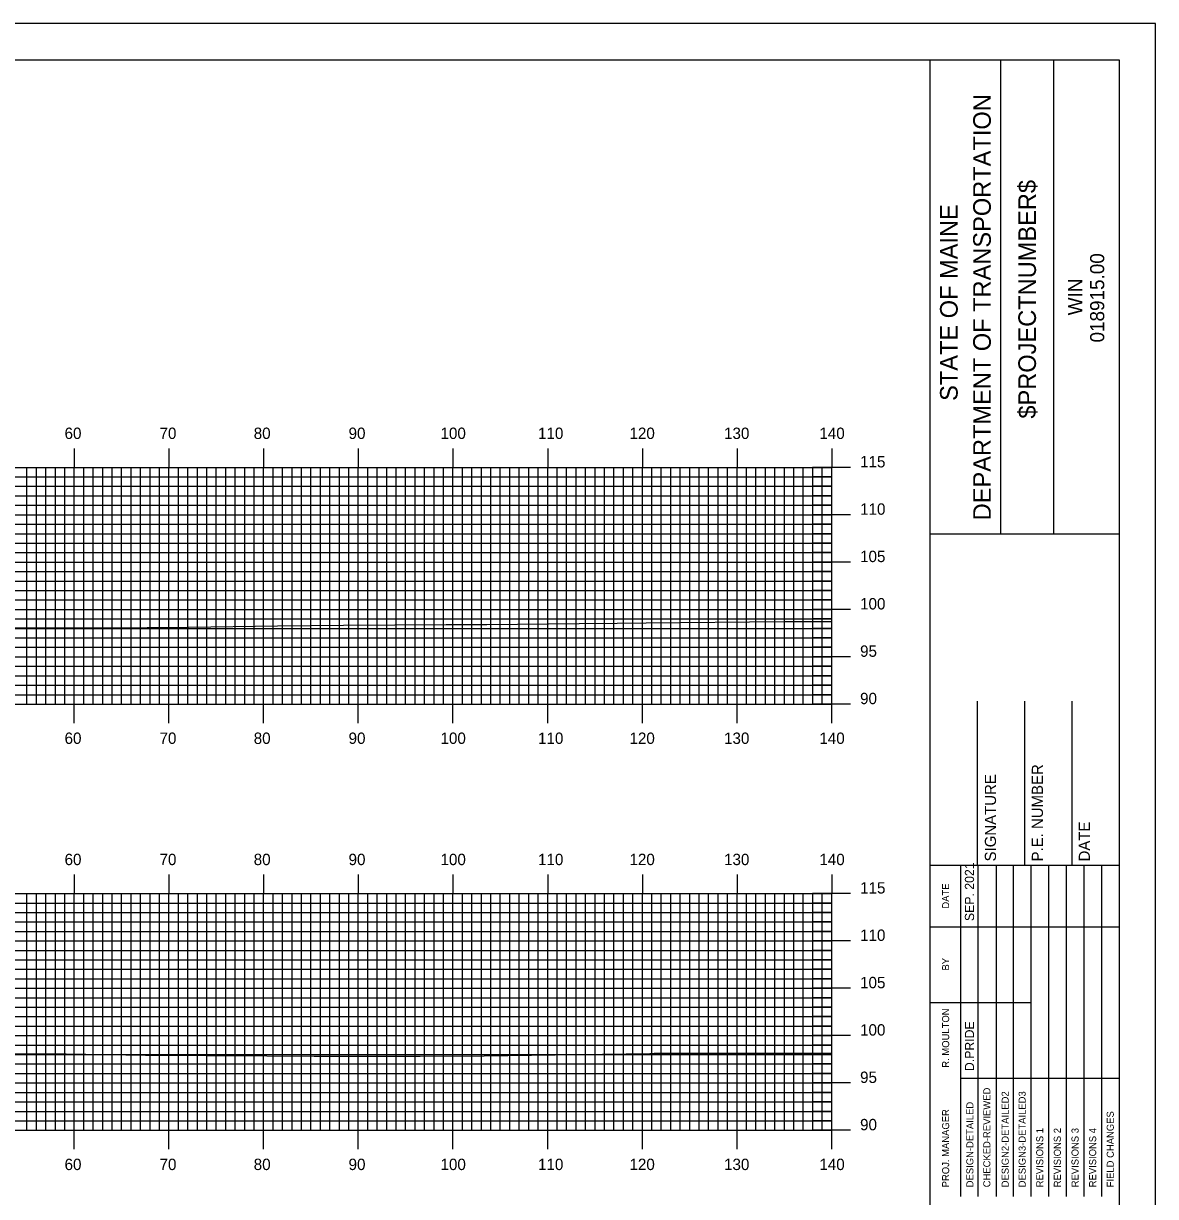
# Model space of a CAD drawing. Extents: x 1764939 to 1765282, y 442591 to 442811.
# Drawn here: x 1765159.5 to 1765279.1, y 442686.7 to 442810.5 of the extents above; entities that cross this region are included whole.
import ezdxf

# ---------------------------------------------------------------- set-up
doc = ezdxf.new("R2010")
doc.units = 0
for name, color, linetype in [('BORDER', 7, 'Continuous'), ('H_V ANNOTATION', 7, 'Continuous'), ('MAJOR', 7, 'Continuous'), ('MINOR', 7, 'Continuous'), ('PLOT BOUNDARY', 7, 'Continuous'), ('S_Roadway_Centerline', 7, 'Continuous')]:
    doc.layers.add(name, color=color, linetype=linetype)

msp = doc.modelspace()

# ---------------------------------------------------------------- linework, layer by layer
at = {"layer": 'BORDER'}
for p, q in [((1765255.26, 442596.67), (1765255.26, 442806.67)), ((1765262.72, 442756.66), (1765262.72, 442806.66)), ((1765268.31, 442756.66), (1765268.31, 442806.66)), ((1765255.26, 442756.65), (1765275.26, 442756.65)), ((1765260.26, 442721.67), (1765260.26, 442738.97)), ((1765265.26, 442721.67), (1765265.26, 442738.97)), ((1765270.26, 442721.67), (1765270.26, 442738.97)), ((1765255.26, 442721.67), (1765275.26, 442721.67))]:
    msp.add_line(p, q, dxfattribs=at)
msp.add_lwpolyline([(1764955.26, 442596.67), (1765275.26, 442596.67), (1765275.26, 442806.67), (1764955.26, 442806.67)], close=True, dxfattribs=at)
for points in [[(1765258.49, 442715.17), (1765258.49, 442721.67)], [(1765260.35, 442686.68), (1765260.35, 442721.67)], [(1765262.22, 442721.67), (1765262.22, 442686.68)], [(1765264.08, 442686.68), (1765264.08, 442721.67)], [(1765265.94, 442686.68), (1765265.94, 442721.67)], [(1765267.81, 442686.68), (1765267.81, 442721.67)], [(1765269.67, 442686.68), (1765269.67, 442721.67)], [(1765271.53, 442686.68), (1765271.53, 442721.67)], [(1765273.4, 442686.68), (1765273.4, 442721.67)], [(1765258.49, 442686.68), (1765258.49, 442720.26)], [(1765255.26, 442715.17), (1765275.26, 442715.17)], [(1765255.26, 442707.17), (1765258.49, 442707.17)], [(1765258.49, 442707.17), (1765265.94, 442707.17)], [(1765258.49, 442699.17), (1765275.26, 442699.17)]]:
    msp.add_lwpolyline(points, dxfattribs=at)
at = {"layer": 'MAJOR'}
for p, q in [((1765164.86, 442765.67), (1765164.86, 442763.67)), ((1765174.86, 442765.67), (1765174.86, 442763.67)), ((1765184.86, 442765.67), (1765184.86, 442763.67)), ((1765194.86, 442765.67), (1765194.86, 442763.67)), ((1765204.86, 442765.67), (1765204.86, 442763.67)), ((1765214.86, 442765.67), (1765214.86, 442763.67)), ((1765224.86, 442765.67), (1765224.86, 442763.67)), ((1765234.86, 442765.67), (1765234.86, 442763.67)), ((1765244.86, 442765.67), (1765244.86, 442763.67)), ((1764964.86, 442763.67), (1765244.86, 442763.67)), ((1764964.86, 442763.67), (1765244.86, 442763.67)), ((1765164.86, 442738.67), (1765164.86, 442763.67)), ((1765174.86, 442738.67), (1765174.86, 442763.67)), ((1765184.86, 442738.67), (1765184.86, 442763.67)), ((1765194.86, 442738.67), (1765194.86, 442763.67)), ((1765204.86, 442738.67), (1765204.86, 442763.67)), ((1765214.86, 442738.67), (1765214.86, 442763.67)), ((1765224.86, 442738.67), (1765224.86, 442763.67)), ((1765234.86, 442738.67), (1765234.86, 442763.67)), ((1765246.86, 442763.67), (1765242.85, 442763.67)), ((1765244.86, 442738.67), (1765244.86, 442763.67)), ((1765244.86, 442738.67), (1765244.86, 442763.67)), ((1764964.86, 442758.67), (1765244.86, 442758.67)), ((1765246.86, 442758.67), (1765242.85, 442758.67)), ((1764964.86, 442753.67), (1765244.86, 442753.67)), ((1765246.86, 442753.67), (1765242.85, 442753.67)), ((1764964.86, 442748.67), (1765244.86, 442748.67)), ((1765246.86, 442748.67), (1765242.85, 442748.67)), ((1764964.86, 442743.67), (1765244.86, 442743.67)), ((1765246.86, 442743.67), (1765242.85, 442743.67)), ((1764964.86, 442738.67), (1765244.86, 442738.67)), ((1764964.86, 442738.67), (1765244.86, 442738.67)), ((1765164.86, 442736.66), (1765164.86, 442738.67)), ((1765174.86, 442736.66), (1765174.86, 442738.67)), ((1765184.86, 442736.66), (1765184.86, 442738.67)), ((1765194.86, 442736.66), (1765194.86, 442738.67)), ((1765204.86, 442736.66), (1765204.86, 442738.67)), ((1765214.86, 442736.66), (1765214.86, 442738.67)), ((1765224.86, 442736.66), (1765224.86, 442738.67)), ((1765234.86, 442736.66), (1765234.86, 442738.67)), ((1765246.86, 442738.67), (1765242.85, 442738.67)), ((1765244.86, 442736.66), (1765244.86, 442738.67)), ((1765164.86, 442720.67), (1765164.86, 442718.67)), ((1765174.86, 442720.67), (1765174.86, 442718.67)), ((1765184.86, 442720.67), (1765184.86, 442718.67)), ((1765194.86, 442720.67), (1765194.86, 442718.67)), ((1765204.86, 442720.67), (1765204.86, 442718.67)), ((1765214.86, 442720.67), (1765214.86, 442718.67)), ((1765224.86, 442720.67), (1765224.86, 442718.67)), ((1765234.86, 442720.67), (1765234.86, 442718.67)), ((1765244.86, 442720.67), (1765244.86, 442718.67)), ((1764964.86, 442718.67), (1765244.86, 442718.67)), ((1764964.86, 442718.67), (1765244.86, 442718.67)), ((1765164.86, 442693.67), (1765164.86, 442718.67)), ((1765174.86, 442693.67), (1765174.86, 442718.67)), ((1765184.86, 442693.67), (1765184.86, 442718.67)), ((1765194.86, 442693.67), (1765194.86, 442718.67)), ((1765204.86, 442693.67), (1765204.86, 442718.67)), ((1765214.86, 442693.67), (1765214.86, 442718.67)), ((1765224.86, 442693.67), (1765224.86, 442718.67)), ((1765234.86, 442693.67), (1765234.86, 442718.67)), ((1765246.86, 442718.67), (1765242.85, 442718.67)), ((1765244.86, 442693.67), (1765244.86, 442718.67)), ((1765244.86, 442693.67), (1765244.86, 442718.67)), ((1764964.86, 442713.67), (1765244.86, 442713.67)), ((1765246.86, 442713.67), (1765242.85, 442713.67)), ((1764964.86, 442708.67), (1765244.86, 442708.67)), ((1765246.86, 442708.67), (1765242.85, 442708.67)), ((1764964.86, 442703.67), (1765244.86, 442703.67)), ((1765246.86, 442703.67), (1765242.85, 442703.67)), ((1764964.86, 442698.67), (1765244.86, 442698.67)), ((1765246.86, 442698.67), (1765242.85, 442698.67)), ((1764964.86, 442693.67), (1765244.86, 442693.67)), ((1764964.86, 442693.67), (1765244.86, 442693.67)), ((1765164.86, 442691.66), (1765164.86, 442693.67)), ((1765174.86, 442691.66), (1765174.86, 442693.67)), ((1765184.86, 442691.66), (1765184.86, 442693.67)), ((1765194.86, 442691.66), (1765194.86, 442693.67)), ((1765204.86, 442691.66), (1765204.86, 442693.67)), ((1765214.86, 442691.66), (1765214.86, 442693.67)), ((1765224.86, 442691.66), (1765224.86, 442693.67)), ((1765234.86, 442691.66), (1765234.86, 442693.67)), ((1765246.86, 442693.67), (1765242.85, 442693.67)), ((1765244.86, 442691.66), (1765244.86, 442693.67))]:
    msp.add_line(p, q, dxfattribs=at)
at = {"layer": 'MINOR'}
for p, q in [((1765159.86, 442738.67), (1765159.86, 442763.67)), ((1765160.86, 442738.67), (1765160.86, 442763.67)), ((1765161.86, 442738.67), (1765161.86, 442763.67)), ((1765162.86, 442738.67), (1765162.86, 442763.67)), ((1765163.86, 442738.67), (1765163.86, 442763.67)), ((1765165.86, 442738.67), (1765165.86, 442763.67)), ((1765166.86, 442738.67), (1765166.86, 442763.67)), ((1765167.86, 442738.67), (1765167.86, 442763.67)), ((1765168.86, 442738.67), (1765168.86, 442763.67)), ((1765169.86, 442738.67), (1765169.86, 442763.67)), ((1765170.86, 442738.67), (1765170.86, 442763.67)), ((1765171.86, 442738.67), (1765171.86, 442763.67)), ((1765172.86, 442738.67), (1765172.86, 442763.67)), ((1765173.86, 442738.67), (1765173.86, 442763.67)), ((1765175.86, 442738.67), (1765175.86, 442763.67)), ((1765176.86, 442738.67), (1765176.86, 442763.67)), ((1765177.86, 442738.67), (1765177.86, 442763.67)), ((1765178.86, 442738.67), (1765178.86, 442763.67)), ((1765179.86, 442738.67), (1765179.86, 442763.67)), ((1765180.86, 442738.67), (1765180.86, 442763.67)), ((1765181.86, 442738.67), (1765181.86, 442763.67)), ((1765182.86, 442738.67), (1765182.86, 442763.67)), ((1765183.86, 442738.67), (1765183.86, 442763.67)), ((1765185.86, 442738.67), (1765185.86, 442763.67)), ((1765186.86, 442738.67), (1765186.86, 442763.67)), ((1765187.86, 442738.67), (1765187.86, 442763.67)), ((1765188.86, 442738.67), (1765188.86, 442763.67)), ((1765189.86, 442738.67), (1765189.86, 442763.67)), ((1765190.86, 442738.67), (1765190.86, 442763.67)), ((1765191.86, 442738.67), (1765191.86, 442763.67)), ((1765192.86, 442738.67), (1765192.86, 442763.67)), ((1765193.86, 442738.67), (1765193.86, 442763.67)), ((1765195.86, 442738.67), (1765195.86, 442763.67)), ((1765196.86, 442738.67), (1765196.86, 442763.67)), ((1765197.86, 442738.67), (1765197.86, 442763.67)), ((1765198.86, 442738.67), (1765198.86, 442763.67)), ((1765199.86, 442738.67), (1765199.86, 442763.67)), ((1765200.86, 442738.67), (1765200.86, 442763.67)), ((1765201.86, 442738.67), (1765201.86, 442763.67)), ((1765202.86, 442738.67), (1765202.86, 442763.67)), ((1765203.86, 442738.67), (1765203.86, 442763.67)), ((1765205.86, 442738.67), (1765205.86, 442763.67)), ((1765206.86, 442738.67), (1765206.86, 442763.67)), ((1765207.86, 442738.67), (1765207.86, 442763.67)), ((1765208.86, 442738.67), (1765208.86, 442763.67)), ((1765209.86, 442738.67), (1765209.86, 442763.67)), ((1765210.86, 442738.67), (1765210.86, 442763.67)), ((1765211.86, 442738.67), (1765211.86, 442763.67)), ((1765212.86, 442738.67), (1765212.86, 442763.67)), ((1765213.86, 442738.67), (1765213.86, 442763.67)), ((1765215.86, 442738.67), (1765215.86, 442763.67)), ((1765216.86, 442738.67), (1765216.86, 442763.67)), ((1765217.86, 442738.67), (1765217.86, 442763.67)), ((1765218.86, 442738.67), (1765218.86, 442763.67)), ((1765219.86, 442738.67), (1765219.86, 442763.67)), ((1765220.86, 442738.67), (1765220.86, 442763.67)), ((1765221.86, 442738.67), (1765221.86, 442763.67)), ((1765222.86, 442738.67), (1765222.86, 442763.67)), ((1765223.86, 442738.67), (1765223.86, 442763.67)), ((1765225.86, 442738.67), (1765225.86, 442763.67)), ((1765226.86, 442738.67), (1765226.86, 442763.67)), ((1765227.86, 442738.67), (1765227.86, 442763.67)), ((1765228.86, 442738.67), (1765228.86, 442763.67)), ((1765229.86, 442738.67), (1765229.86, 442763.67)), ((1765230.86, 442738.67), (1765230.86, 442763.67)), ((1765231.86, 442738.67), (1765231.86, 442763.67)), ((1765232.86, 442738.67), (1765232.86, 442763.67)), ((1765233.86, 442738.67), (1765233.86, 442763.67)), ((1765235.86, 442738.67), (1765235.86, 442763.67)), ((1765236.86, 442738.67), (1765236.86, 442763.67)), ((1765237.86, 442738.67), (1765237.86, 442763.67)), ((1765238.86, 442738.67), (1765238.86, 442763.67)), ((1765239.86, 442738.67), (1765239.86, 442763.67)), ((1765240.86, 442738.67), (1765240.86, 442763.67)), ((1765241.86, 442738.67), (1765241.86, 442763.67)), ((1765242.86, 442738.67), (1765242.86, 442763.67)), ((1765243.86, 442738.67), (1765243.86, 442763.67)), ((1764964.86, 442762.67), (1765244.86, 442762.67)), ((1765244.86, 442762.67), (1765242.85, 442762.67)), ((1764964.86, 442761.67), (1765244.86, 442761.67)), ((1765244.86, 442761.67), (1765242.85, 442761.67)), ((1764964.86, 442760.67), (1765244.86, 442760.67)), ((1765244.86, 442760.67), (1765242.85, 442760.67)), ((1764964.86, 442759.67), (1765244.86, 442759.67)), ((1765244.86, 442759.67), (1765242.85, 442759.67)), ((1764964.86, 442757.67), (1765244.86, 442757.67)), ((1765244.86, 442757.67), (1765242.85, 442757.67)), ((1764964.86, 442756.67), (1765244.86, 442756.67)), ((1765244.86, 442756.67), (1765242.85, 442756.67)), ((1764964.86, 442755.67), (1765244.86, 442755.67)), ((1765244.86, 442755.67), (1765242.85, 442755.67)), ((1764964.86, 442754.67), (1765244.86, 442754.67)), ((1765244.86, 442754.67), (1765242.85, 442754.67)), ((1764964.86, 442752.67), (1765244.86, 442752.67)), ((1765244.86, 442752.67), (1765242.85, 442752.67)), ((1764964.86, 442751.67), (1765244.86, 442751.67)), ((1765244.86, 442751.67), (1765242.85, 442751.67)), ((1764964.86, 442750.67), (1765244.86, 442750.67)), ((1765244.86, 442750.67), (1765242.85, 442750.67)), ((1764964.86, 442749.67), (1765244.86, 442749.67)), ((1765244.86, 442749.67), (1765242.85, 442749.67)), ((1764964.86, 442747.67), (1765244.86, 442747.67)), ((1765244.86, 442747.67), (1765242.85, 442747.67)), ((1764964.86, 442746.67), (1765244.86, 442746.67)), ((1765244.86, 442746.67), (1765242.85, 442746.67)), ((1764964.86, 442745.67), (1765244.86, 442745.67)), ((1765244.86, 442745.67), (1765242.85, 442745.67)), ((1764964.86, 442744.67), (1765244.86, 442744.67)), ((1765244.86, 442744.67), (1765242.85, 442744.67)), ((1764964.86, 442742.67), (1765244.86, 442742.67)), ((1765244.86, 442742.67), (1765242.85, 442742.67)), ((1764964.86, 442741.67), (1765244.86, 442741.67)), ((1765244.86, 442741.67), (1765242.85, 442741.67)), ((1764964.86, 442740.67), (1765244.86, 442740.67)), ((1765244.86, 442740.67), (1765242.85, 442740.67)), ((1764964.86, 442739.67), (1765244.86, 442739.67)), ((1765244.86, 442739.67), (1765242.85, 442739.67)), ((1765159.86, 442693.67), (1765159.86, 442718.67)), ((1765160.86, 442693.67), (1765160.86, 442718.67)), ((1765161.86, 442693.67), (1765161.86, 442718.67)), ((1765162.86, 442693.67), (1765162.86, 442718.67)), ((1765163.86, 442693.67), (1765163.86, 442718.67)), ((1765165.86, 442693.67), (1765165.86, 442718.67)), ((1765166.86, 442693.67), (1765166.86, 442718.67)), ((1765167.86, 442693.67), (1765167.86, 442718.67)), ((1765168.86, 442693.67), (1765168.86, 442718.67)), ((1765169.86, 442693.67), (1765169.86, 442718.67)), ((1765170.86, 442693.67), (1765170.86, 442718.67)), ((1765171.86, 442693.67), (1765171.86, 442718.67)), ((1765172.86, 442693.67), (1765172.86, 442718.67)), ((1765173.86, 442693.67), (1765173.86, 442718.67)), ((1765175.86, 442693.67), (1765175.86, 442718.67)), ((1765176.86, 442693.67), (1765176.86, 442718.67)), ((1765177.86, 442693.67), (1765177.86, 442718.67)), ((1765178.86, 442693.67), (1765178.86, 442718.67)), ((1765179.86, 442693.67), (1765179.86, 442718.67)), ((1765180.86, 442693.67), (1765180.86, 442718.67)), ((1765181.86, 442693.67), (1765181.86, 442718.67)), ((1765182.86, 442693.67), (1765182.86, 442718.67)), ((1765183.86, 442693.67), (1765183.86, 442718.67)), ((1765185.86, 442693.67), (1765185.86, 442718.67)), ((1765186.86, 442693.67), (1765186.86, 442718.67)), ((1765187.86, 442693.67), (1765187.86, 442718.67)), ((1765188.86, 442693.67), (1765188.86, 442718.67)), ((1765189.86, 442693.67), (1765189.86, 442718.67)), ((1765190.86, 442693.67), (1765190.86, 442718.67)), ((1765191.86, 442693.67), (1765191.86, 442718.67)), ((1765192.86, 442693.67), (1765192.86, 442718.67)), ((1765193.86, 442693.67), (1765193.86, 442718.67)), ((1765195.86, 442693.67), (1765195.86, 442718.67)), ((1765196.86, 442693.67), (1765196.86, 442718.67)), ((1765197.86, 442693.67), (1765197.86, 442718.67)), ((1765198.86, 442693.67), (1765198.86, 442718.67)), ((1765199.86, 442693.67), (1765199.86, 442718.67)), ((1765200.86, 442693.67), (1765200.86, 442718.67)), ((1765201.86, 442693.67), (1765201.86, 442718.67)), ((1765202.86, 442693.67), (1765202.86, 442718.67)), ((1765203.86, 442693.67), (1765203.86, 442718.67)), ((1765205.86, 442693.67), (1765205.86, 442718.67)), ((1765206.86, 442693.67), (1765206.86, 442718.67)), ((1765207.86, 442693.67), (1765207.86, 442718.67)), ((1765208.86, 442693.67), (1765208.86, 442718.67)), ((1765209.86, 442693.67), (1765209.86, 442718.67)), ((1765210.86, 442693.67), (1765210.86, 442718.67)), ((1765211.86, 442693.67), (1765211.86, 442718.67)), ((1765212.86, 442693.67), (1765212.86, 442718.67)), ((1765213.86, 442693.67), (1765213.86, 442718.67)), ((1765215.86, 442693.67), (1765215.86, 442718.67)), ((1765216.86, 442693.67), (1765216.86, 442718.67)), ((1765217.86, 442693.67), (1765217.86, 442718.67)), ((1765218.86, 442693.67), (1765218.86, 442718.67)), ((1765219.86, 442693.67), (1765219.86, 442718.67)), ((1765220.86, 442693.67), (1765220.86, 442718.67)), ((1765221.86, 442693.67), (1765221.86, 442718.67)), ((1765222.86, 442693.67), (1765222.86, 442718.67)), ((1765223.86, 442693.67), (1765223.86, 442718.67)), ((1765225.86, 442693.67), (1765225.86, 442718.67)), ((1765226.86, 442693.67), (1765226.86, 442718.67)), ((1765227.86, 442693.67), (1765227.86, 442718.67)), ((1765228.86, 442693.67), (1765228.86, 442718.67)), ((1765229.86, 442693.67), (1765229.86, 442718.67)), ((1765230.86, 442693.67), (1765230.86, 442718.67)), ((1765231.86, 442693.67), (1765231.86, 442718.67)), ((1765232.86, 442693.67), (1765232.86, 442718.67)), ((1765233.86, 442693.67), (1765233.86, 442718.67)), ((1765235.86, 442693.67), (1765235.86, 442718.67)), ((1765236.86, 442693.67), (1765236.86, 442718.67)), ((1765237.86, 442693.67), (1765237.86, 442718.67)), ((1765238.86, 442693.67), (1765238.86, 442718.67)), ((1765239.86, 442693.67), (1765239.86, 442718.67)), ((1765240.86, 442693.67), (1765240.86, 442718.67)), ((1765241.86, 442693.67), (1765241.86, 442718.67)), ((1765242.86, 442693.67), (1765242.86, 442718.67)), ((1765243.86, 442693.67), (1765243.86, 442718.67)), ((1764964.86, 442717.67), (1765244.86, 442717.67)), ((1764964.86, 442716.67), (1765244.86, 442716.67)), ((1765244.86, 442717.67), (1765242.85, 442717.67)), ((1765244.86, 442716.67), (1765242.85, 442716.67)), ((1764964.86, 442715.67), (1765244.86, 442715.67)), ((1765244.86, 442715.67), (1765242.85, 442715.67)), ((1764964.86, 442714.67), (1765244.86, 442714.67)), ((1765244.86, 442714.67), (1765242.85, 442714.67)), ((1764964.86, 442712.67), (1765244.86, 442712.67)), ((1764964.86, 442711.67), (1765244.86, 442711.67)), ((1765244.86, 442712.67), (1765242.85, 442712.67)), ((1765244.86, 442711.67), (1765242.85, 442711.67)), ((1764964.86, 442710.67), (1765244.86, 442710.67)), ((1765244.86, 442710.67), (1765242.85, 442710.67)), ((1764964.86, 442709.67), (1765244.86, 442709.67)), ((1765244.86, 442709.67), (1765242.85, 442709.67)), ((1764964.86, 442707.67), (1765244.86, 442707.67)), ((1764964.86, 442706.67), (1765244.86, 442706.67)), ((1765244.86, 442707.67), (1765242.85, 442707.67)), ((1765244.86, 442706.67), (1765242.85, 442706.67)), ((1764964.86, 442705.67), (1765244.86, 442705.67)), ((1765244.86, 442705.67), (1765242.85, 442705.67)), ((1764964.86, 442704.67), (1765244.86, 442704.67)), ((1765244.86, 442704.67), (1765242.85, 442704.67)), ((1764964.86, 442702.67), (1765244.86, 442702.67)), ((1764964.86, 442701.67), (1765244.86, 442701.67)), ((1765244.86, 442702.67), (1765242.85, 442702.67)), ((1765244.86, 442701.67), (1765242.85, 442701.67)), ((1764964.86, 442700.67), (1765244.86, 442700.67)), ((1765244.86, 442700.67), (1765242.85, 442700.67)), ((1764964.86, 442699.67), (1765244.86, 442699.67)), ((1765244.86, 442699.67), (1765242.85, 442699.67)), ((1764964.86, 442697.67), (1765244.86, 442697.67)), ((1764964.86, 442696.67), (1765244.86, 442696.67)), ((1765244.86, 442697.67), (1765242.85, 442697.67)), ((1765244.86, 442696.67), (1765242.85, 442696.67)), ((1764964.86, 442695.67), (1765244.86, 442695.67)), ((1765244.86, 442695.67), (1765242.85, 442695.67)), ((1764964.86, 442694.67), (1765244.86, 442694.67)), ((1765244.86, 442694.67), (1765242.85, 442694.67))]:
    msp.add_line(p, q, dxfattribs=at)
at = {"layer": 'PLOT BOUNDARY'}
msp.add_lwpolyline([(1764939.07, 442590.55), (1765279.07, 442590.55), (1765279.07, 442810.55), (1764939.07, 442810.55)], close=True, dxfattribs=at)
at = {"layer": 'S_Roadway_Centerline'}
for points in [[(1765150.36, 442746.73), (1765161.32, 442746.72), (1765168.17, 442746.74), (1765176.91, 442746.81), (1765186.31, 442746.93), (1765193.31, 442747), (1765204.13, 442747.09), (1765208.43, 442747.08), (1765218.18, 442747.18), (1765222.21, 442747.23), (1765225.26, 442747.25), (1765239.79, 442747.38), (1765244.86, 442747.41)], [(1765154.28, 442701.76), (1765164, 442701.76), (1765172.39, 442701.6), (1765185.19, 442701.54), (1765190.18, 442701.5), (1765201.39, 442701.5), (1765208.15, 442701.54), (1765225.64, 442701.79), (1765226.11, 442701.8), (1765226.72, 442701.8), (1765243.9, 442701.82), (1765244.86, 442701.82)]]:
    msp.add_lwpolyline(points, dxfattribs=at)

# ---------------------------------------------------------------- texts
at = {"layer": 'BORDER'}
for s, height, p in [('DEPARTMENT OF TRANSPORTATION', 1.8635, (1765261.67, 442758.08)), ('$PROJECTNUMBER$', 1.8635, (1765266.44, 442768.82)), ('STATE OF MAINE', 1.8635, (1765258.17, 442770.69)), ('018915.00', 1.491, (1765273.65, 442776.86)), ('WIN', 1.491, (1765271.33, 442779.73)), ('P.E. NUMBER', 1.1811, (1765267.18, 442722.06)), ('SIGNATURE', 1.181, (1765262.22, 442722.06)), ('DATE', 1.181, (1765272.14, 442722.06)), ('SEP. 2021', 0.969, (1765259.9, 442715.76)), ('DATE', 0.743, (1765257.27, 442717.08)), ('BY', 0.743, (1765257.27, 442710.54)), ('R. MOULTON', 0.745, (1765257.27, 442700.28)), ('D.PRIDE', 0.969, (1765259.9, 442699.92)), ('CHECKED-REVIEWED', 0.7455, (1765261.62, 442687.65)), ('DESIGN2-DETAILED2', 0.7455, (1765263.56, 442687.65)), ('DESIGN3-DETAILED3', 0.7455, (1765265.35, 442687.65)), ('PROJ. MANAGER', 0.7455, (1765257.27, 442687.65)), ('DESIGN-DETAILED', 0.7455, (1765259.83, 442687.65)), ('FIELD CHANGES', 0.7455, (1765274.66, 442687.65)), ('REVISIONS 1', 0.7455, (1765267.21, 442687.65)), ('REVISIONS 2', 0.7455, (1765269.07, 442687.65)), ('REVISIONS 3', 0.7455, (1765270.94, 442687.65)), ('REVISIONS 4', 0.7455, (1765272.8, 442687.65))]:
    msp.add_text(s, height=height, rotation=90, dxfattribs=at).set_placement(p)
at = {"layer": 'H_V ANNOTATION'}
for s, p in [('60', (1765163.83, 442766.67)), ('70', (1765173.86, 442766.67)), ('80', (1765183.81, 442766.67)), ('90', (1765193.83, 442766.67)), ('100', (1765203.54, 442766.67)), ('110', (1765213.84, 442766.67)), ('120', (1765223.5, 442766.67)), ('130', (1765233.49, 442766.67)), ('140', (1765243.56, 442766.67)), ('115', (1765247.86, 442763.67)), ('110', (1765247.86, 442758.67)), ('105', (1765247.86, 442753.67)), ('100', (1765247.86, 442748.67)), ('95', (1765247.86, 442743.67)), ('90', (1765247.86, 442738.67)), ('60', (1765163.83, 442734.47)), ('70', (1765173.86, 442734.47)), ('80', (1765183.81, 442734.47)), ('90', (1765193.83, 442734.47)), ('100', (1765203.54, 442734.47)), ('110', (1765213.84, 442734.47)), ('120', (1765223.5, 442734.47)), ('130', (1765233.49, 442734.47)), ('140', (1765243.56, 442734.47)), ('60', (1765163.83, 442721.67)), ('70', (1765173.86, 442721.67)), ('80', (1765183.81, 442721.67)), ('90', (1765193.83, 442721.67)), ('100', (1765203.54, 442721.67)), ('110', (1765213.84, 442721.67)), ('120', (1765223.5, 442721.67)), ('130', (1765233.49, 442721.67)), ('140', (1765243.56, 442721.67)), ('115', (1765247.86, 442718.67)), ('110', (1765247.86, 442713.67)), ('105', (1765247.86, 442708.67)), ('100', (1765247.86, 442703.67)), ('95', (1765247.86, 442698.67)), ('90', (1765247.86, 442693.67)), ('60', (1765163.83, 442689.47)), ('70', (1765173.86, 442689.47)), ('80', (1765183.81, 442689.47)), ('90', (1765193.83, 442689.47)), ('100', (1765203.54, 442689.47)), ('110', (1765213.84, 442689.47)), ('120', (1765223.5, 442689.47)), ('130', (1765233.49, 442689.47)), ('140', (1765243.56, 442689.47))]:
    msp.add_text(s, height=1.2, dxfattribs=at).set_placement(p)

doc.saveas('drawing.dxf')
